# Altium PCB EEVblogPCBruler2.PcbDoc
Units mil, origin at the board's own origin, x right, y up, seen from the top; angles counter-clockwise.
Board outline 7000 x 836.61 mil, 2 copper layers (Top Layer, Bottom Layer); 0 components, 0 nets, 17 pads, 0 vias.
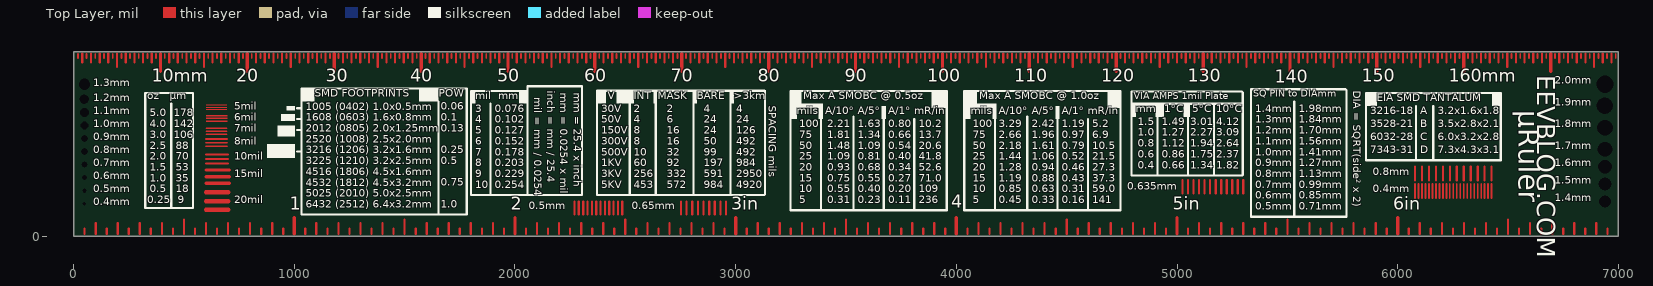
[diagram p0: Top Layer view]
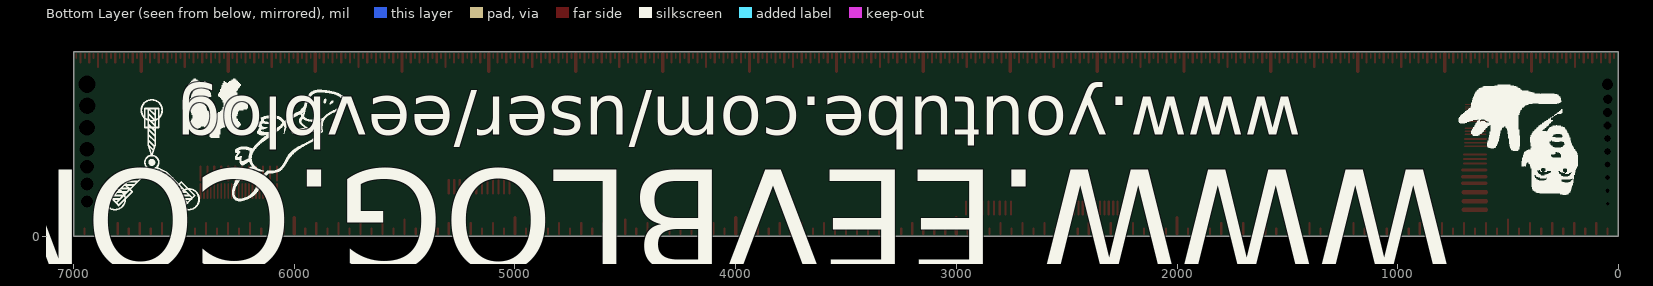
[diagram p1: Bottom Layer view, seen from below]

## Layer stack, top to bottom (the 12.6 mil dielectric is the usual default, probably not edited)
Top Layer: signal copper 1.4
Dielectric: dielectric 12.6, FR-4, Dk 4.8
Bottom Layer: signal copper 1.4

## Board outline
0,0 7000,0 7000,836.61 0,836.61

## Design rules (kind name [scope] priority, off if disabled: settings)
Clearance [All] p1: gap=10
PolygonConnect [All] p1: connectstyle=Relief reliefconductorwidth=10 reliefentries=4 polygonreliefangle="90 Angle"
RoutingVias [All] p1: holewidth=28 width=50 viastyle="Through Hole" minholewidth=28 minwidth=50 maxholewidth=28 maxwidth=50
SilkscreenOverComponentPads [All] p1: minsilkscreentomaskgap=10
SolderMaskExpansion [All] p1: expansion=4
Width [All] p1: maxlimit=10 minlimit=10 preferedwidth=10
27 further rules are at their usual default settings.

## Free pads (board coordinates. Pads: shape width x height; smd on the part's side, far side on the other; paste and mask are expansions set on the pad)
  rect 0x0 hole 15.75 unplated mask+2: 1(49.21,147.64)
  rect 0x0 hole 19.68 unplated mask+2: 2(49.21,206.69)
  rect 0x0 hole 23.62 unplated mask+2: 3(49.21,265.75)
  rect 0x0 hole 27.56 unplated mask+2: 4(49.21,324.8)
  rect 0x0 hole 31.5 unplated mask+2: 5(49.21,442.91) 6(49.21,383.86)
  rect 0x0 hole 35.43 unplated mask+2: 7(49.21,501.97)
  rect 0x0 hole 39.37 unplated mask+2: 8(49.21,561.02)
  rect 0x0 hole 43.31 unplated mask+2: 9(49.21,620.08)
  rect 0x0 hole 51.18 unplated mask+2: 10(49.21,688.98)
  rect 0x0 hole 55.12 unplated mask+2: 11(6938.98,157.48)
  rect 0x0 hole 59.06 unplated mask+2: 12(6938.98,236.22)
  rect 0x0 hole 62.99 unplated mask+2: 13(6938.98,314.96)
  rect 0x0 hole 66.93 unplated mask+2: 14(6938.98,393.7)
  rect 0x0 hole 70.87 unplated mask+2: 15(6938.98,492.13)
  rect 0x0 hole 74.8 unplated mask+2: 16(6938.98,590.55)
  rect 0x0 hole 78.74 unplated mask+2: 17(6938.98,688.98)

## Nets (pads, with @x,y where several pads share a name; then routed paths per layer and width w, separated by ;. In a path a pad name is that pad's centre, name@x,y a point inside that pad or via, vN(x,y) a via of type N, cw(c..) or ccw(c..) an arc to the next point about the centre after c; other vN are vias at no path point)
copper on no net: | length 23943.6
  Top Layer w5: 600,575 695,575 ; 600,585 695,585 ; 600,595 695,595
  Top Layer w6: 600,522 696,522 ; 600,534 696,534 ; 600,546 696,546
  Top Layer w7: 602,462 693,462 ; 602,476 693,476 ; 602,490 693,490
  Top Layer w8: 19.68,807.09 19.68,826.77 ; 59.06,807.09 59.06,826.77 ; 98.43,807.09 98.43,826.77 ; 137.8,807.09 137.8,826.77 ; 177.17,807.09 177.17,826.77 ; 216.54,807.09 216.54,826.77 ; 255.91,807.09 255.91,826.77 ; 295.28,807.09 295.28,826.77 ; 334.65,807.09 334.65,826.77 ; 374.02,807.09 374.02,826.77 ; 413.39,807.09 413.39,826.77 ; 452.76,807.09 452.76,826.77 ; 492.13,807.09 492.13,826.77 ; 531.5,807.09 531.5,826.77 ; 570.87,807.09 570.87,826.77 ; 600,408 696,408 ; 600,424 696,424 ; 600,440 696,440 ; 610.24,807.09 610.24,826.77 ; 649.61,807.09 649.61,826.77 ; 688.98,807.09 688.98,826.77 ; 728.35,807.09 728.35,826.77 ; 767.72,807.09 767.72,826.77 ; 807.09,807.09 807.09,826.77 ; 846.46,807.09 846.46,826.77 ; 885.83,807.09 885.83,826.77 ; 925.2,807.09 925.2,826.77 ; 964.57,807.09 964.57,826.77 ; 1003.94,807.09 1003.94,826.77 ; 1043.31,807.09 1043.31,826.77 ; 1082.68,807.09 1082.68,826.77 ; 1122.05,807.09 1122.05,826.77 ; 1161.42,807.09 1161.42,826.77 ; 1200.79,807.09 1200.79,826.77 ; 1240.16,807.09 1240.16,826.77 ; 1279.53,807.09 1279.53,826.77 ; 1318.9,807.09 1318.9,826.77 ; 1358.27,807.09 1358.27,826.77 ; 1397.64,807.09 1397.64,826.77 ; 1437.01,807.09 1437.01,826.77 ; 1476.38,807.09 1476.38,826.77 ; 1515.75,807.09 1515.75,826.77 ; 1555.12,807.09 1555.12,826.77 ; 1594.49,807.09 1594.49,826.77 ; 1633.86,807.09 1633.86,826.77 ; 1673.23,807.09 1673.23,826.77 ; 1712.6,807.09 1712.6,826.77 ; 1751.97,807.09 1751.97,826.77 ; 1791.34,807.09 1791.34,826.77 ; 1830.71,807.09 1830.71,826.77 ; 1870.08,807.09 1870.08,826.77 ; 1909.45,807.09 1909.45,826.77 ; 1948.82,807.09 1948.82,826.77 ; 1988.19,807.09 1988.19,826.77 ; 2027.56,807.09 2027.56,826.77 ; 2066.93,807.09 2066.93,826.77 ; 2106.3,807.09 2106.3,826.77 ; 2145.67,807.09 2145.67,826.77 ; 2185.04,807.09 2185.04,826.77 ; 2224.41,807.09 2224.41,826.77 ; 2263.78,807.09 2263.78,826.77 ; 2303.15,807.09 2303.15,826.77 ; 2342.52,807.09 2342.52,826.77 ; 2381.89,807.09 2381.89,826.77 ; 2421.26,807.09 2421.26,826.77 ; 2460.63,807.09 2460.63,826.77 ; 2500,807.09 2500,826.77 ; 2539.37,807.09 2539.37,826.77 ; 2578.74,807.09 2578.74,826.77 ; 2618.11,807.09 2618.11,826.77 ; 2657.48,807.09 2657.48,826.77 ; 2696.85,807.09 2696.85,826.77 ; 2736.22,807.09 2736.22,826.77 ; 2775.59,807.09 2775.59,826.77 ; 2814.96,807.09 2814.96,826.77 ; 2854.33,807.09 2854.33,826.77 ; 2893.7,807.09 2893.7,826.77 ; 2933.07,807.09 2933.07,826.77 ; 2972.44,807.09 2972.44,826.77 ; 3011.81,807.09 3011.81,826.77 ; 3051.18,807.09 3051.18,826.77 ; 3090.55,807.09 3090.55,826.77 ; 3129.92,807.09 3129.92,826.77 ; 3169.29,807.09 3169.29,826.77 ; 3208.66,807.09 3208.66,826.77 ; 3248.03,807.09 3248.03,826.77 ; 3287.4,807.09 3287.4,826.77 ; 3326.77,807.09 3326.77,826.77 ; 3366.14,807.09 3366.14,826.77 ; 3405.51,807.09 3405.51,826.77 ; 3444.88,807.09 3444.88,826.77 ; 3484.25,807.09 3484.25,826.77 ; 3523.62,807.09 3523.62,826.77 ; 3562.99,807.09 3562.99,826.77 ; 3602.36,807.09 3602.36,826.77 ; 3641.73,807.09 3641.73,826.77 ; 3681.1,807.09 3681.1,826.77 ; 3720.47,807.09 3720.47,826.77 ; 3759.84,807.09 3759.84,826.77 ; 3799.21,807.09 3799.21,826.77 ; 3838.58,807.09 3838.58,826.77 ; 3877.95,807.09 3877.95,826.77 ; 3917.32,807.09 3917.32,826.77 ; 3956.69,807.09 3956.69,826.77 ; 3996.06,807.09 3996.06,826.77 ; 4035.43,807.09 4035.43,826.77 ; 4074.8,807.09 4074.8,826.77 ; 4114.17,807.09 4114.17,826.77 ; 4153.54,807.09 4153.54,826.77 ; 4192.91,807.09 4192.91,826.77 ; 4232.28,807.09 4232.28,826.77 ; 4271.65,807.09 4271.65,826.77 ; 4311.02,807.09 4311.02,826.77 ; 4350.39,807.09 4350.39,826.77 ; 4389.76,807.09 4389.76,826.77 ; 4429.13,807.09 4429.13,826.77 ; 4468.5,807.09 4468.5,826.77 ; 4507.87,807.09 4507.87,826.77 ; 4547.24,807.09 4547.24,826.77 ; 4586.61,807.09 4586.61,826.77 ; 4625.98,807.09 4625.98,826.77 ; 4665.35,807.09 4665.35,826.77 ; 4704.72,807.09 4704.72,826.77 ; 4744.09,807.09 4744.09,826.77 ; 4783.46,807.09 4783.46,826.77 ; 4822.83,807.09 4822.83,826.77 ; 4862.2,807.09 4862.2,826.77 ; 4901.57,807.09 4901.57,826.77 ; 4940.94,807.09 4940.94,826.77 ; 4980.31,807.09 4980.31,826.77 ; 5019.69,807.09 5019.69,826.77 ; 5059.06,807.09 5059.06,826.77 ; 5098.43,807.09 5098.43,826.77 ; 5137.8,807.09 5137.8,826.77 ; 5177.17,807.09 5177.17,826.77 ; 5216.54,807.09 5216.54,826.77 ; 5255.91,807.09 5255.91,826.77 ; 5295.28,807.09 5295.28,826.77 ; 5334.65,807.09 5334.65,826.77 ; 5374.02,807.09 5374.02,826.77 ; 5413.39,807.09 5413.39,826.77 ; 5452.76,807.09 5452.76,826.77 ; 5492.13,807.09 5492.13,826.77 ; 5531.5,807.09 5531.5,826.77 ; 5570.87,807.09 5570.87,826.77 ; 5610.24,807.09 5610.24,826.77 ; 5649.61,807.09 5649.61,826.77 ; 5688.98,807.09 5688.98,826.77 ; 5728.35,807.09 5728.35,826.77 ; 5767.72,807.09 5767.72,826.77 ; 5807.09,807.09 5807.09,826.77 ; 5846.46,807.09 5846.46,826.77 ; 5885.83,807.09 5885.83,826.77 ; 5925.2,807.09 5925.2,826.77 ; 5964.57,807.09 5964.57,826.77 ; 6003.94,807.09 6003.94,826.77 ; 6043.31,807.09 6043.31,826.77 ; 6078.74,173.23 6078.74,236.22 ; 6082.68,807.09 6082.68,826.77 ; 6094.49,173.23 6094.49,236.22 ; 6110.24,173.23 6110.24,236.22 ; 6122.05,807.09 6122.05,826.77 ; 6125.98,173.23 6125.98,236.22 ; 6141.73,173.23 6141.73,236.22 ; 6157.48,173.23 6157.48,236.22 ; 6161.42,807.09 6161.42,826.77 ; 6173.23,173.23 6173.23,236.22 ; 6188.98,173.23 6188.98,236.22 ; 6200.79,807.09 6200.79,826.77 ; 6204.72,173.23 6204.72,236.22 ; 6220.47,173.23 6220.47,236.22 ; 6236.22,173.23 6236.22,236.22 ; 6240.16,807.09 6240.16,826.77 ; 6251.97,173.23 6251.97,236.22 ; 6267.72,173.23 6267.72,236.22 ; 6279.53,807.09 6279.53,826.77 ; 6283.46,173.23 6283.46,236.22 ; 6299.21,173.23 6299.21,236.22 ; 6314.96,173.23 6314.96,236.22 ; 6318.9,807.09 6318.9,826.77 ; 6330.71,173.23 6330.71,236.22 ; 6346.46,173.23 6346.46,236.22 ; 6358.27,807.09 6358.27,826.77 ; 6362.2,173.23 6362.2,236.22 ; 6377.95,173.23 6377.95,236.22 ; 6393.7,173.23 6393.7,236.22 ; 6397.64,807.09 6397.64,826.77 ; 6409.45,173.23 6409.45,236.22 ; 6425.2,173.23 6425.2,236.22 ; 6437.01,807.09 6437.01,826.77 ; 6476.38,807.09 6476.38,826.77 ; 6515.75,807.09 6515.75,826.77 ; 6555.12,807.09 6555.12,826.77 ; 6594.49,807.09 6594.49,826.77 ; 6633.86,807.09 6633.86,826.77 ; 6673.23,807.09 6673.23,826.77 ; 6712.6,807.09 6712.6,826.77 ; 6751.97,807.09 6751.97,826.77 ; 6791.34,807.09 6791.34,826.77 ; 6830.71,807.09 6830.71,826.77 ; 6870.08,807.09 6870.08,826.77 ; 6909.45,807.09 6909.45,826.77 ; 6948.82,807.09 6948.82,826.77 ; 6988.19,807.09 6988.19,826.77
  Top Layer w10: 39.37,787.4 39.37,826.77 ; 50,10 50,35 ; 78.74,787.4 78.74,826.77 ; 100,10 100,60 ; 118.11,787.4 118.11,826.77 ; 150,10 150,35 ; 157.48,787.4 157.48,826.77 ; 196.85,767.72 196.85,826.77 ; 200,10 200,60 ; 236.22,787.4 236.22,826.77 ; 250,10 250,35 ; 275.59,787.4 275.59,826.77 ; 300,10 300,60 ; 314.96,787.4 314.96,826.77 ; 350,10 350,35 ; 354.33,787.4 354.33,826.77 ; 400,10 400,60 ; 433.07,787.4 433.07,826.77 ; 450,10 450,35 ; 472.44,787.4 472.44,826.77 ; 500,10 500,75 ; 511.81,787.4 511.81,826.77 ; 550,10 550,35 ; 551.18,787.4 551.18,826.77 ; 590.55,767.72 590.55,826.77 ; 600,10 600,60 ; 600,330 700,330 ; 600,350 700,350 ; 600,370 700,370 ; 629.92,787.4 629.92,826.77 ; 650,10 650,35 ; 669.29,787.4 669.29,826.77 ; 700,10 700,60 ; 708.66,787.4 708.66,826.77 ; 748.03,787.4 748.03,826.77 ; 750,10 750,35 ; 800,10 800,60 ; 826.77,787.4 826.77,826.77 ; 850,10 850,35 ; 866.14,787.4 866.14,826.77 ; 900,10 900,60 ; 905.51,787.4 905.51,826.77 ; 944.88,787.4 944.88,826.77 ; 950,10 950,35 ; 984.25,767.72 984.25,826.77 ; 1023.62,787.4 1023.62,826.77 ; 1062.99,787.4 1062.99,826.77 ; 1102.36,787.4 1102.36,826.77 ; 1141.73,787.4 1141.73,826.77 ; 1220.47,787.4 1220.47,826.77 ; 1259.84,787.4 1259.84,826.77 ; 1299.21,787.4 1299.21,826.77 ; 1338.58,787.4 1338.58,826.77 ; 1377.95,767.72 1377.95,826.77 ; 1417.32,787.4 1417.32,826.77 ; 1456.69,787.4 1456.69,826.77 ; 1496.06,787.4 1496.06,826.77 ; 1535.43,787.4 1535.43,826.77 ; 1614.17,787.4 1614.17,826.77 ; 1653.54,787.4 1653.54,826.77 ; 1692.91,787.4 1692.91,826.77 ; 1732.28,787.4 1732.28,826.77 ; 1771.65,767.72 1771.65,826.77 ; 1811.02,787.4 1811.02,826.77 ; 1850.39,787.4 1850.39,826.77 ; 1889.76,787.4 1889.76,826.77 ; 1929.13,787.4 1929.13,826.77 ; 2007.87,787.4 2007.87,826.77 ; 2047.24,787.4 2047.24,826.77 ; 2050,10 2050,35 ; 2086.61,787.4 2086.61,826.77 ; 2100,10 2100,60 ; 2125.98,787.4 2125.98,826.77 ; 2150,10 2150,35 ; 2165.35,767.72 2165.35,826.77 ; 2200,10 2200,60 ; 2204.72,787.4 2204.72,826.77 ; 2244.09,787.4 2244.09,826.77 ; 2250,10 2250,35 ; 2269.69,98.43 2269.69,157.48 ; 2283.46,787.4 2283.46,826.77 ; 2289.37,98.43 2289.37,157.48 ; 2300,10 2300,60 ; 2309.06,98.43 2309.06,157.48 ; 2322.83,787.4 2322.83,826.77 ; 2328.74,98.43 2328.74,157.48 ; 2348.43,98.43 2348.43,157.48 ; 2350,10 2350,35 ; 2368.11,98.43 2368.11,157.48 ; 2387.8,98.43 2387.8,157.48 ; 2400,10 2400,60 ; 2401.57,787.4 2401.57,826.77 ; 2407.48,98.43 2407.48,157.48 ; 2427.17,98.43 2427.17,157.48 ; 2440.94,787.4 2440.94,826.77 ; 2446.85,98.43 2446.85,157.48 ; 2450,10 2450,35 ; 2466.54,98.43 2466.54,157.48 ; 2480.31,787.4 2480.31,826.77 ; 2486.22,98.43 2486.22,157.48 ; 2500,10 2500,75 ; 2519.69,787.4 2519.69,826.77 ; 2550,10 2550,35 ; 2559.06,767.72 2559.06,826.77 ; 2598.43,787.4 2598.43,826.77 ; 2600,10 2600,60 ; 2637.8,787.4 2637.8,826.77 ; 2650,10 2650,35 ; 2677.17,787.4 2677.17,826.77 ; 2700,10 2700,60 ; 2716.54,787.4 2716.54,826.77 ; 2750,10 2750,35 ; 2751.97,98.43 2751.97,157.48 ; 2777.56,98.43 2777.56,157.48 ; 2795.28,787.4 2795.28,826.77 ; 2800,10 2800,60 ; 2803.15,98.43 2803.15,157.48 ; 2828.74,98.43 2828.74,157.48 ; 2834.65,787.4 2834.65,826.77 ; 2850,10 2850,35 ; 2854.33,98.43 2854.33,157.48 ; 2874.02,787.4 2874.02,826.77 ; 2879.92,98.43 2879.92,157.48 ; 2900,10 2900,60 ; 2905.51,98.43 2905.51,157.48 ; 2913.39,787.4 2913.39,826.77 ; 2931.1,98.43 2931.1,157.48 ; 2950,10 2950,35 ; 2952.76,767.72 2952.76,826.77 ; 2956.69,98.43 2956.69,157.48 ; 2992.13,787.4 2992.13,826.77 ; 3031.5,787.4 3031.5,826.77 ; 3050,10 3050,35 ; 3070.87,787.4 3070.87,826.77 ; 3100,10 3100,60 ; 3110.24,787.4 3110.24,826.77 ; 3150,10 3150,35 ; 3188.98,787.4 3188.98,826.77 ; 3200,10 3200,60 ; 3228.35,787.4 3228.35,826.77 ; 3250,10 3250,35 ; 3267.72,787.4 3267.72,826.77 ; 3300,10 3300,60 ; 3307.09,787.4 3307.09,826.77 ; 3346.46,767.72 3346.46,826.77 ; 3350,10 3350,35 ; 3385.83,787.4 3385.83,826.77 ; 3400,10 3400,60 ; 3425.2,787.4 3425.2,826.77 ; 3450,10 3450,35 ; 3464.57,787.4 3464.57,826.77 ; 3500,10 3500,75 ; 3503.94,787.4 3503.94,826.77 ; 3550,10 3550,35 ; 3582.68,787.4 3582.68,826.77 ; 3600,10 3600,60 ; 3622.05,787.4 3622.05,826.77 ; 3650,10 3650,35 ; 3661.42,787.4 3661.42,826.77 ; 3700,10 3700,60 ; 3700.79,787.4 3700.79,826.77 ; 3740.16,767.72 3740.16,826.77 ; 3750,10 3750,35 ; 3779.53,787.4 3779.53,826.77 ; 3800,10 3800,60 ; 3818.9,787.4 3818.9,826.77 ; 3850,10 3850,35 ; 3858.27,787.4 3858.27,826.77 ; 3897.64,787.4 3897.64,826.77 ; 3900,10 3900,60 ; 3950,10 3950,35 ; 3976.38,787.4 3976.38,826.77 ; 4015.75,787.4 4015.75,826.77 ; 4050,10 4050,35 ; 4055.12,787.4 4055.12,826.77 ; 4094.49,787.4 4094.49,826.77 ; 4100,10 4100,60 ; 4133.86,767.72 4133.86,826.77 ; 4150,10 4150,35 ; 4173.23,787.4 4173.23,826.77 ; 4200,10 4200,60 ; 4212.6,787.4 4212.6,826.77 ; 4250,10 4250,35 ; 4251.97,787.4 4251.97,826.77 ; 4291.34,787.4 4291.34,826.77 ; 4300,10 4300,60 ; 4350,10 4350,35 ; 4370.08,787.4 4370.08,826.77 ; 4400,10 4400,60 ; 4409.45,787.4 4409.45,826.77 ; 4448.82,787.4 4448.82,826.77 ; 4450,10 4450,35 ; 4488.19,787.4 4488.19,826.77 ; 4500,10 4500,75 ; 4527.56,767.72 4527.56,826.77 ; 4550,10 4550,35 ; 4566.93,787.4 4566.93,826.77 ; 4600,10 4600,60 ; 4606.3,787.4 4606.3,826.77 ; 4645.67,787.4 4645.67,826.77 ; 4650,10 4650,35 ; 4685.04,787.4 4685.04,826.77 ; 4700,10 4700,60 ; 4750,10 4750,35 ; 4763.78,787.4 4763.78,826.77 ; 4800,10 4800,60 ; 4803.15,787.4 4803.15,826.77 ; 4842.52,787.4 4842.52,826.77 ; 4850,10 4850,35 ; 4881.89,787.4 4881.89,826.77 ; 4900,10 4900,60 ; 4921.26,767.72 4921.26,826.77 ; 4950,10 4950,35 ; 4960.63,787.4 4960.63,826.77 ; 5000,787.4 5000,826.77 ; 5025,194.68 5025,253.74 ; 5039.37,787.4 5039.37,826.77 ; 5050,10 5050,35 ; 5050,194.68 5050,253.74 ; 5075,194.68 5075,253.74 ; 5078.74,787.4 5078.74,826.77 ; 5100,10 5100,60 ; 5100,194.68 5100,253.74 ; 5125,194.68 5125,253.74 ; 5150,10 5150,35 ; 5150,194.68 5150,253.74 ; 5157.48,787.4 5157.48,826.77 ; 5175,194.68 5175,253.74 ; 5196.85,787.4 5196.85,826.77 ; 5200,10 5200,60 ; 5200,194.68 5200,253.74 ; 5225,194.68 5225,253.74 ; 5236.22,787.4 5236.22,826.77 ; 5250,10 5250,35 ; 5250,194.68 5250,253.74 ; 5275,194.68 5275,253.74 ; 5275.59,787.4 5275.59,826.77 ; 5300,10 5300,60 ; 5300,194.68 5300,253.74 ; 5314.96,767.72 5314.96,826.77 ; 5350,10 5350,35 ; 5354.33,787.4 5354.33,826.77 ; 5393.7,787.4 5393.7,826.77 ; 5400,10 5400,60 ; 5433.07,787.4 5433.07,826.77 ; 5450,10 5450,35 ; 5472.44,787.4 5472.44,826.77 ; 5500,10 5500,75 ; 5550,10 5550,35 ; 5551.18,787.4 5551.18,826.77 ; 5590.55,787.4 5590.55,826.77 ; 5600,10 5600,60 ; 5629.92,787.4 5629.92,826.77 ; 5650,10 5650,35 ; 5669.29,787.4 5669.29,826.77 ; 5700,10 5700,60 ; 5708.66,767.72 5708.66,826.77 ; 5748.03,787.4 5748.03,826.77 ; 5750,10 5750,35 ; 5787.4,787.4 5787.4,826.77 ; 5800,10 5800,60 ; 5826.77,787.4 5826.77,826.77 ; 5850,10 5850,35 ; 5866.14,787.4 5866.14,826.77 ; 5900,10 5900,60 ; 5944.88,787.4 5944.88,826.77 ; 5950,10 5950,35 ; 5984.25,787.4 5984.25,826.77 ; 6023.62,787.4 6023.62,826.77 ; 6050,10 6050,35 ; 6062.99,787.4 6062.99,826.77 ; 6078.74,251.97 6078.74,314.96 ; 6100,10 6100,60 ; 6102.36,767.72 6102.36,826.77 ; 6110.24,251.97 6110.24,314.96 ; 6141.73,251.97 6141.73,314.96 ; 6141.73,787.4 6141.73,826.77 ; 6150,10 6150,35 ; 6173.23,251.97 6173.23,314.96 ; 6181.1,787.4 6181.1,826.77 ; 6200,10 6200,60 ; 6204.72,251.97 6204.72,314.96 ; 6220.47,787.4 6220.47,826.77 ; 6236.22,251.97 6236.22,314.96 ; 6250,10 6250,35 ; 6259.84,787.4 6259.84,826.77 ; 6267.72,251.97 6267.72,314.96 ; 6299.21,251.97 6299.21,314.96 ; 6300,10 6300,60 ; 6330.71,251.97 6330.71,314.96 ; 6338.58,787.4 6338.58,826.77 ; 6350,10 6350,35 ; 6362.2,251.97 6362.2,314.96 ; 6377.95,787.4 6377.95,826.77 ; 6393.7,251.97 6393.7,314.96 ; 6400,10 6400,60 ; 6417.32,787.4 6417.32,826.77 ; 6425.2,251.97 6425.2,314.96 ; 6450,10 6450,35 ; 6456.69,787.4 6456.69,826.77 ; 6496.06,767.72 6496.06,826.77 ; 6500,10 6500,75 ; 6535.43,787.4 6535.43,826.77 ; 6550,10 6550,35 ; 6574.8,787.4 6574.8,826.77 ; 6600,10 6600,60 ; 6614.17,787.4 6614.17,826.77 ; 6650,10 6650,35 ; 6653.54,787.4 6653.54,826.77 ; 6700,10 6700,60 ; 6732.28,787.4 6732.28,826.77 ; 6750,10 6750,35 ; 6771.65,787.4 6771.65,826.77 ; 6800,10 6800,60 ; 6811.02,787.4 6811.02,826.77 ; 6850,10 6850,35 ; 6850.39,787.4 6850.39,826.77 ; 6889.76,767.72 6889.76,826.77 ; 6900,10 6900,60 ; 6929.13,787.4 6929.13,826.77 ; 6950,10 6950,35 ; 6968.5,787.4 6968.5,826.77 ; 1050,10 1050,35 1050,10 ; 1100,10 1100,60 1100,10 ; 1150,10 1150,35 1150,10 ; 1200,10 1200,60 1200,10 ; 1250,10 1250,35 1250,10 ; 1300,10 1300,60 1300,10 ; 1350,10 1350,35 1350,10 ; 1400,10 1400,60 1400,10 ; 1450,10 1450,35 1450,10 ; 1500,10 1500,75 1500,10 ; 1550,10 1550,35 1550,10 ; 1600,10 1600,60 1600,10 ; 1650,10 1650,35 1650,10 ; 1700,10 1700,60 1700,10 ; 1750,10 1750,35 1750,10 ; 1800,10 1800,60 1800,10 ; 1850,10 1850,35 1850,10 ; 1900,10 1900,60 1900,10 ; 1950,10 1950,35 1950,10
  Top Layer w15: 393.7,748.03 393.7,826.77 ; 600,239.84 705,239.84 ; 600,269.84 705,269.84 ; 600,299.84 705,299.84 ; 787.4,748.03 787.4,826.77 ; 1000,10 1000,85 ; 1181.1,748.03 1181.1,826.77 ; 1574.8,748.03 1574.8,826.77 ; 1968.5,748.03 1968.5,826.77 ; 2362.2,748.03 2362.2,826.77 ; 2755.91,748.03 2755.91,826.77 ; 3000,10 3000,85 ; 3149.61,748.03 3149.61,826.77 ; 3543.31,748.03 3543.31,826.77 ; 3937.01,748.03 3937.01,826.77 ; 4000,10 4000,85 ; 4330.71,748.03 4330.71,826.77 ; 4724.41,748.03 4724.41,826.77 ; 5000,10 5000,85 ; 5118.11,748.03 5118.11,826.77 ; 5511.81,748.03 5511.81,826.77 ; 5905.51,748.03 5905.51,826.77 ; 6000,10 6000,85 ; 6299.21,748.03 6299.21,826.77 ; 6692.91,748.03 6692.91,826.77 ; 2000,10 2000,85 2000,10
  Top Layer w20: 600,120 700,120 ; 600,159.37 700,159.37 ; 600,199.37 700,199.37

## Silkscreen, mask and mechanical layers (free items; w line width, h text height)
Top Overlay:
  rectangle: 2972.44,600.39 2992.13,659.45
  rectangle: 2805.12,600.39 2824.8,659.45
  rectangle: 2627.95,600.39 2637.8,659.45
  rectangle: 2460.63,600.39 2539.37,659.45
  rectangle: 2372.05,600.39 2411.42,659.45
  rectangle: 4685.04,580.71 4744.09,658.61
  rectangle: 4035.43,589.28 4094.49,658.61
  rectangle: 3887.8,580.71 3956.69,658.61
  rectangle: 3252.19,589.28 3297.24,654.46
  rectangle: 4035.43,531.5 4064.96,590.55
  rectangle: 4163.39,530.81 4183.07,600.39
  rectangle: 4448.82,531.5 4468.5,590.55
  rectangle: 4045.28,580.71 4173.23,600.39
  rectangle: 3257.87,580.71 3385.83,600.39
  rectangle: 3661.42,531.5 3681.1,590.55
  rectangle: 3375.98,530.8 3395.67,600.39
  rectangle: 3248.03,531.5 3277.56,590.55
  rectangle: 6427.17,590.55 6466.54,649.61
  rectangle: 5856.3,590.55 5905.51,649.61
  rectangle: 2017.72,600.39 2057.09,657.92
  rectangle: 1801.18,600.39 1820.87,657.92
  rectangle: 4803.15,589.02 4910.1,600.39
  rectangle: 4793.31,541.34 4812.99,599.75
  rectangle: 4901.57,541.34 4940.94,600.39
  rectangle: 5029.53,540.65 5059.06,600.39
  rectangle: 1564.09,609.76 1653.54,668.82
  rectangle: 1032.6,609.76 1091.65,668.82
  rectangle: 877.09,353.86 1003.07,416.85
  rectangle: 924.33,452.28 1003.07,501.5
  rectangle: 940.08,521.18 1003.07,552.68
  rectangle: 963.7,570.39 1003.07,590.08
  lines w10: 442.91,127.95 442.91,600.39 ; 1012.91,383.39 1032.6,383.39 ; 1012.91,481.81 1032.6,481.81 ; 1012.91,531.02 1032.6,531.02 ; 1012.91,580.24 1032.6,580.24 ; 1653.54,97.95 1653.54,609.76 ; 1889.76,187.01 1889.76,600.39 ; 2057.09,206.69 2057.09,677.61 ; 2057.09,657.92 1801.18,657.92 1801.18,187.01 2057.09,187.01 ; 2519.69,187.01 2519.69,659.45 ; 2637.8,187.01 2637.8,658.56 ; 2809.14,187.01 2809.14,658.56 ; 2976.25,187.01 2976.25,659.45 ; 3252.19,654.46 3248.03,658.61 ; 3387.28,119.56 3387.28,530.8 ; 3533.46,118.11 3533.46,541.34 ; 3671.26,118.11 3671.26,530.86 ; 3809.06,118.11 3809.06,531.5 ; 4039.59,654.46 4035.43,658.61 ; 4174.68,119.56 4174.68,530.81 ; 4320.87,118.11 4320.87,541.34 ; 4458.66,118.11 4458.66,530.86 ; 4596.46,118.11 4596.46,531.5 ; 4793.31,580.71 4793.31,656.02 5293.64,656.02 ; 4911.42,275.59 4911.42,600.39 ; 5049.21,275.59 5049.21,600.39 ; 5167.32,275.59 5167.32,599.5 ; 5298.12,580.71 5298.12,651.54 ; 5531.5,88.58 5531.5,610.24 ; 6082.68,344.49 6082.68,590.55 ; 6161.42,344.49 6161.42,590.55 ; 2057.09,187.01 2303.15,187.01 2303.15,679.13 2057.09,679.13 2057.09,187.01 ; 2976.25,659.45 3131.25,659.45 3132.66,658.04 3132.66,189.75 3129.92,187.01 2962.6,187.01 2372.05,187.01 2372.05,659.45 2976.25,659.45 ; 3248.03,658.61 3956.69,658.61 3956.69,118.11 3248.03,118.11 3248.03,658.61 ; 4035.43,658.61 4035.43,118.11 4744.09,118.11 4744.09,658.61 4035.43,658.61 ; 324.8,127.95 324.8,649.61 541.34,649.61 541.34,127.95 324.8,127.95 ; 1032.6,97.95 1781.5,97.95 1781.5,668.82 1032.6,668.82 1032.6,97.95 ; 4793.31,275.59 5295.28,275.59 5298.12,278.43 5298.12,599.5 5299.01,600.39 4793.31,600.39 4793.31,275.59 ; 5334.65,88.58 5767.72,88.58 5767.72,661.46 5763.32,665.86 5334.65,665.86 5334.65,88.58 ; 5856.3,344.49 6466.54,344.49 6466.54,649.61 5856.3,649.61 5856.3,344.49
  text "EEVBLOG.COM" at 6604.33,728.35 h137.8 r270
  text "10mm" at 354.33,679.13 h98.43
  text "20" at 738.19,679.13 h98.43
  text "30" at 1141.73,679.13 h98.43
  text "40" at 1525.59,679.13 h98.43
  text "50" at 1919.29,679.13 h98.43
  text "60" at 2312.99,679.13 h98.43
  text "70" at 2706.69,679.13 h98.43
  text "80" at 3100.39,679.13 h98.43
  text "90" at 3494.09,679.13 h98.43
  text "100" at 3868.11,679.13 h98.43
  text "110" at 4261.81,679.13 h98.43
  text "120" at 4655.51,679.13 h98.43
  text "130" at 5049.21,679.13 h98.43
  text "150" at 5836.61,679.13 h98.43
  text "160mm" at 6230.32,679.13 h98.43
  text "2.0mm" at 6712.6,679.13 h59.06
  text "140" at 5442.91,675.7 h98.43
  text "1.3mm" at 88.58,669.29 h59.06
  text "inch = mm / 25.4" at 2135.83,659.45 h59.06 r270
  text "DIA = SQRT(side² x 2)" at 5787.4,659.45 h59.06 r270
  text "mm = 0.0254 x mil" at 2194.88,649.61 h59.06 r270
  text "mm = 25.4 x inch" at 2253.94,649.61 h59.06 r270
  text "mil = mm / 0.0254" at 2076.77,629.92 h59.06 r270
  text "SMD FOOTPRINTS" at 1091.65,619.61 h59.06
  text "POW" at 1653.54,620.08 h59.06
  text "SQ PIN to DIAmm" at 5344.49,620.08 h55.12
  text "oz   µm" at 334.65,610.24 h59.06
  text "mil  mm" at 1820.87,610.24 h59.06
  text "V" at 2421.26,610.24 h59.06
  text "INT" at 2539.37,610.24 h59.06
  text "MASK" at 2647.64,610.24 h59.06
  text "BARE" at 2824.8,610.24 h59.06
  text ">3km" at 2992.13,610.24 h59.06
  text "Max A SMOBC @ 0.5oz" at 3307.09,610.24 h59.06
  text "Max A SMOBC @ 1.0oz" at 4104.33,610.24 h59.06
  text "VIA AMPS 1mil Plate" at 4803.15,610.24 h55.12
  text "1.2mm" at 88.58,600.39 h59.06
  text "EIA SMD TANTALUM" at 5905.51,600.39 h59.06
  text "SPACING mils" at 3139.76,590.55 h59.06 r270
  text "1.9mm" at 6712.6,580.71 h59.06
  text "µRuler" at 6515.75,570.87 h157.48 r270
  text "5mil" at 728.35,561.02 h59.06
  text "1005 (0402) 1.0x0.5mm" at 1052.28,560.55 h59.06
  text "0.06" at 1663.39,561.02 h59.06
  text "3" at 1820.87,551.18 h59.06
  text "0.076" at 1909.45,551.18 h59.06
  text "30V" at 2391.73,551.18 h59.06
  text "2" at 2539.37,551.18 h59.06
  text "2" at 2687.01,551.18 h59.06
  text "4" at 2854.33,551.18 h59.06
  text "4" at 3001.97,551.18 h59.06
  text "mm" at 4812.99,551.18 h59.06
  text "1°C" at 4940.94,551.18 h59.06
  text "5°C" at 5068.9,551.18 h59.06
  text "10°C" at 5177.17,551.18 h59.06
  text "1.4mm" at 5354.33,551.18 h59.06
  text "1.98mm" at 5551.18,551.18 h59.06
  text "1.1mm" at 88.58,541.34 h59.06
  text "mils" at 3277.56,541.34 h59.06
  text "A/10°" at 3405.51,541.34 h59.06
  text "A/5°" at 3553.15,541.34 h59.06
  text "A/1°" at 3690.94,541.34 h59.06
  text "mR/in" at 3809.06,541.34 h59.06
  text "mils" at 4064.96,541.34 h59.06
  text "A/10°" at 4192.91,541.34 h59.06
  text "A/5°" at 4340.55,541.34 h59.06
  text "A/1°" at 4478.35,541.34 h59.06
  text "mR/in" at 4596.46,541.34 h59.06
  text "3216-18" at 5875.98,541.34 h59.06
  text "A" at 6102.36,541.34 h59.06
  text "3.2x1.6x1.8" at 6181.1,541.34 h59.06
  text "5.0" at 344.49,531.5 h59.06
  text "178" at 452.76,531.5 h59.06
  text "6mil" at 728.35,511.81 h59.06
  text "0.1" at 1663.39,511.81 h59.06
  text "1608 (0603) 1.6x0.8mm" at 1052.28,511.34 h59.06
  text "4" at 1820.87,501.97 h59.06
  text "0.102" at 1909.45,501.97 h59.06
  text "50V" at 2391.73,501.97 h59.06
  text "4" at 2539.37,501.97 h59.06
  text "6" at 2687.01,501.97 h59.06
  text "24" at 2854.33,501.97 h59.06
  text "24" at 3001.97,501.97 h59.06
  text "1.3mm" at 5354.33,501.97 h59.06
  text "1.84mm" at 5551.18,501.97 h59.06
  text "1.5" at 4822.83,492.13 h59.06
  text "1.49" at 4931.1,492.13 h59.06
  text "3.01" at 5059.06,492.13 h59.06
  text "4.12" at 5177.17,492.13 h59.06
  text "1.0mm" at 88.58,482.28 h59.06
  text "4.0" at 344.49,482.28 h59.06
  text "142" at 452.76,482.28 h59.06
  text "100" at 3287.4,482.28 h59.06
  text "2.21" at 3415.35,482.28 h59.06
  text "1.63" at 3553.15,482.28 h59.06
  text "0.80" at 3690.94,482.28 h59.06
  text "10.2" at 3828.74,482.28 h59.06
  text "100" at 4074.8,482.28 h59.06
  text "3.29" at 4192.91,482.28 h59.06
  text "2.42" at 4340.55,482.28 h59.06
  text "1.19" at 4478.35,482.28 h59.06
  text "5.2" at 4616.14,482.28 h59.06
  text "3528-21" at 5875.98,482.28 h59.06
  text "B" at 6102.36,482.28 h59.06
  text "3.5x2.8x2.1" at 6181.1,482.28 h59.06
  text "1.8mm" at 6712.6,482.28 h59.06
  text "7mil" at 728.35,462.6 h59.06
  text "0.13" at 1663.39,462.6 h59.06
  text "2012 (0805) 2.0x1.25mm" at 1052.28,462.13 h59.06
  text "5" at 1820.87,452.76 h59.06
  text "0.127" at 1909.45,452.76 h59.06
  text "150V" at 2391.73,452.76 h59.06
  text "8" at 2539.37,452.76 h59.06
  text "16" at 2687.01,452.76 h59.06
  text "24" at 2854.33,452.76 h59.06
  text "126" at 3001.97,452.76 h59.06
  text "1.2mm" at 5354.33,452.76 h59.06
  text "1.70mm" at 5551.18,452.76 h59.06
  text "1.0" at 4822.83,442.91 h59.06
  text "1.27" at 4931.1,442.91 h59.06
  text "2.27" at 5059.06,442.91 h59.06
  text "3.09" at 5177.17,442.91 h59.06
  text "3.0" at 344.49,433.07 h59.06
  text "106" at 452.76,433.07 h59.06
  text "75" at 3287.4,433.07 h59.06
  text "1.81" at 3415.35,433.07 h59.06
  text "1.34" at 3553.15,433.07 h59.06
  text "0.66" at 3690.94,433.07 h59.06
  text "13.7" at 3828.74,433.07 h59.06
  text "75" at 4074.8,433.07 h59.06
  text "2.66" at 4192.91,433.07 h59.06
  text "1.96" at 4340.55,433.07 h59.06
  text "0.97" at 4478.35,433.07 h59.06
  text "6.9" at 4616.14,433.07 h59.06
  text "0.9mm" at 88.58,423.23 h59.06
  text "6032-28" at 5875.98,423.23 h59.06
  text "C" at 6102.36,423.23 h59.06
  text "6.0x3.2x2.8" at 6181.1,423.23 h59.06
  text "2520 (1008) 2.5x2.0mm" at 1052.28,412.91 h59.06
  text "8mil" at 728.35,403.54 h59.06
  text "6" at 1820.87,403.54 h59.06
  text "0.152" at 1909.45,403.54 h59.06
  text "300V" at 2391.73,403.54 h59.06
  text "8" at 2539.37,403.54 h59.06
  text "16" at 2687.01,403.54 h59.06
  text "50" at 2854.33,403.54 h59.06
  text "492" at 3001.97,403.54 h59.06
  text "1.1mm" at 5354.33,403.54 h59.06
  text "1.56mm" at 5551.18,403.54 h59.06
  text "0.8" at 4822.83,393.7 h59.06
  text "1.12" at 4931.1,393.7 h59.06
  text "1.94" at 5059.06,393.7 h59.06
  text "2.64" at 5177.17,393.7 h59.06
  text "2.5" at 344.49,383.86 h59.06
  text "88" at 462.6,383.86 h59.06
  text "50" at 3287.4,383.86 h59.06
  text "1.48" at 3415.35,383.86 h59.06
  text "1.09" at 3553.15,383.86 h59.06
  text "0.54" at 3690.94,383.86 h59.06
  text "20.6" at 3828.74,383.86 h59.06
  text "50" at 4074.8,383.86 h59.06
  text "2.18" at 4192.91,383.86 h59.06
  text "1.61" at 4340.55,383.86 h59.06
  text "0.79" at 4478.35,383.86 h59.06
  text "10.5" at 4616.14,383.86 h59.06
  text "1.7mm" at 6712.6,383.86 h59.06
  text "0.8mm" at 88.58,364.17 h59.06
  text "3216 (1206) 3.2x1.6mm" at 1052.28,363.7 h59.06
  text "0.25" at 1663.39,364.17 h59.06
  text "7343-31" at 5875.98,364.17 h59.06
  text "D" at 6102.36,364.17 h59.06
  text "7.3x4.3x3.1" at 6181.1,364.17 h59.06
  text "7" at 1820.87,354.33 h59.06
  text "0.178" at 1909.45,354.33 h59.06
  text "500V" at 2391.73,354.33 h59.06
  text "10" at 2539.37,354.33 h59.06
  text "32" at 2687.01,354.33 h59.06
  text "99" at 2854.33,354.33 h59.06
  text "492" at 3001.97,354.33 h59.06
  text "1.0mm" at 5354.33,354.33 h59.06
  text "1.41mm" at 5551.18,354.33 h59.06
  text "0.6" at 4822.83,344.49 h59.06
  text "0.86" at 4931.1,344.49 h59.06
  text "1.75" at 5059.06,344.49 h59.06
  text "2.37" at 5177.17,344.49 h59.06
  text "2.0" at 344.49,334.65 h59.06
  text "70" at 462.6,334.65 h59.06
  text "10mil" at 728.35,334.65 h59.06
  text "25" at 3287.4,334.65 h59.06
  text "1.09" at 3415.35,334.65 h59.06
  text "0.81" at 3553.15,334.65 h59.06
  text "0.40" at 3690.94,334.65 h59.06
  text "41.8" at 3828.74,334.65 h59.06
  text "25" at 4074.8,334.65 h59.06
  text "1.44" at 4192.91,334.65 h59.06
  text "1.06" at 4340.55,334.65 h59.06
  text "0.52" at 4478.35,334.65 h59.06
  text "21.5" at 4616.14,334.65 h59.06
  text "0.5" at 1663.39,314.96 h59.06
  text "3225 (1210) 3.2x2.5mm" at 1052.28,314.49 h59.06
  text "0.7mm" at 88.58,305.12 h59.06
  text "8" at 1820.87,305.12 h59.06
  text "0.203" at 1909.45,305.12 h59.06
  text "1KV" at 2391.73,305.12 h59.06
  text "60" at 2539.37,305.12 h59.06
  text "92" at 2687.01,305.12 h59.06
  text "197" at 2854.33,305.12 h59.06
  text "984" at 3001.97,305.12 h59.06
  text "0.9mm" at 5354.33,305.12 h59.06
  text "1.27mm" at 5551.18,305.12 h59.06
  text "1.6mm" at 6712.6,305.12 h59.06
  text "0.4" at 4822.83,295.28 h59.06
  text "0.66" at 4931.1,295.28 h59.06
  text "1.34" at 5059.06,295.28 h59.06
  text "1.82" at 5177.17,295.28 h59.06
  text "1.5" at 344.49,285.43 h59.06
  text "53" at 462.6,285.43 h59.06
  text "20" at 3287.4,285.43 h59.06
  text "0.93" at 3415.35,285.43 h59.06
  text "0.68" at 3553.15,285.43 h59.06
  text "0.34" at 3690.94,285.43 h59.06
  text "52.6" at 3828.74,285.43 h59.06
  text "20" at 4074.8,285.43 h59.06
  text "1.28" at 4192.91,285.43 h59.06
  text "0.94" at 4340.55,285.43 h59.06
  text "0.46" at 4478.35,285.43 h59.06
  text "27.3" at 4616.14,285.43 h59.06
  text "0.8mm" at 5885.83,265.75 h59.06
  text "4516 (1806) 4.5x1.6mm" at 1052.28,265.28 h59.06
  text "15mil" at 728.35,255.91 h59.06
  text "9" at 1820.87,255.91 h59.06
  text "0.229" at 1909.45,255.91 h59.06
  text "3KV" at 2391.73,255.91 h59.06
  text "256" at 2539.37,255.91 h59.06
  text "332" at 2687.01,255.91 h59.06
  text "591" at 2854.33,255.91 h59.06
  text "2950" at 3001.97,255.91 h59.06
  text "0.8mm" at 5354.33,255.91 h59.06
  text "1.13mm" at 5551.18,255.91 h59.06
  text "0.6mm" at 88.58,246.06 h59.06
  text "1.0" at 344.49,236.22 h59.06
  text "35" at 462.6,236.22 h59.06
  text "15" at 3287.4,236.22 h59.06
  text "0.75" at 3415.35,236.22 h59.06
  text "0.55" at 3553.15,236.22 h59.06
  text "0.27" at 3690.94,236.22 h59.06
  text "71.0" at 3828.74,236.22 h59.06
  text "15" at 4074.8,236.22 h59.06
  text "1.19" at 4192.91,236.22 h59.06
  text "0.88" at 4340.55,236.22 h59.06
  text "0.43" at 4478.35,236.22 h59.06
  text "37.3" at 4616.14,236.22 h59.06
  text "1.5mm" at 6712.6,226.38 h59.06
  text "0.75" at 1663.39,216.54 h59.06
  text "4532 (1812) 4.5x3.2mm" at 1052.28,216.06 h59.06
  text "10" at 1820.87,206.69 h59.06
  text "0.254" at 1909.45,206.69 h59.06
  text "5KV" at 2391.73,206.69 h59.06
  text "453" at 2539.37,206.69 h59.06
  text "572" at 2687.01,206.69 h59.06
  text "984" at 2854.33,206.69 h59.06
  text "4920" at 3001.97,206.69 h59.06
  text "0.7mm" at 5354.33,206.69 h59.06
  text "0.99mm" at 5551.18,206.69 h59.06
  text "0.635mm" at 4775,200 h59.06
  text "0.5mm" at 88.58,187.01 h59.06
  text "0.5" at 344.49,187.01 h59.06
  text "18" at 462.6,187.01 h59.06
  text "10" at 3287.4,187.01 h59.06
  text "0.55" at 3415.35,187.01 h59.06
  text "0.40" at 3553.15,187.01 h59.06
  text "0.20" at 3690.94,187.01 h59.06
  text "109" at 3828.74,187.01 h59.06
  text "10" at 4074.8,187.01 h59.06
  text "0.85" at 4192.91,187.01 h59.06
  text "0.63" at 4340.55,187.01 h59.06
  text "0.31" at 4478.35,187.01 h59.06
  text "59.0" at 4616.14,187.01 h59.06
  text "0.4mm" at 5885.83,187.01 h59.06
  text "5025 (2010) 5.0x2.5mm" at 1052.28,166.85 h59.06
  text "0.6mm" at 5354.33,157.48 h59.06
  text "0.85mm" at 5551.18,157.48 h59.06
  text "1.4mm" at 6712.6,147.64 h59.06
  text "0.25" at 334.65,137.8 h59.06
  text "9" at 472.44,137.8 h59.06
  text "20mil" at 728.35,137.8 h59.06
  text "5" at 3287.4,137.8 h59.06
  text "0.31" at 3415.35,137.8 h59.06
  text "0.23" at 3553.15,137.8 h59.06
  text "0.11" at 3690.94,137.8 h59.06
  text "236" at 3828.74,137.8 h59.06
  text "5" at 4074.8,137.8 h59.06
  text "0.45" at 4192.91,137.8 h59.06
  text "0.33" at 4340.55,137.8 h59.06
  text "0.16" at 4478.35,137.8 h59.06
  text "141" at 4616.14,137.8 h59.06
  text "0.4mm" at 88.58,127.95 h59.06
  text "6432 (2512) 6.4x3.2mm" at 1052.28,117.64 h59.06
  text "1.0" at 1663.39,118.11 h59.06
  text "0.5mm" at 2062.2,110.24 h59.06
  text "0.65mm" at 2528.74,110.24 h59.06
  text "4" at 3976.38,108.27 h98.43
  text "0.5mm" at 5354.33,108.27 h59.06
  text "0.71mm" at 5551.18,108.27 h59.06
  text "1" at 980,100 h98.43
  text "2" at 1980,100 h98.43
  text "3in" at 2980,100 h98.43
  text "5in" at 4980,100 h98.43
  text "6in" at 5980,100 h98.43
Bottom Overlay:
  drawing of 2038 lines, arcs and shapes, not listed
  text "www.youtube.com/user/eevblog" at 1437.01,708.66 h393.7 r180
  text "WWW.EEVBLOG.COM" at 748.03,452.76 h787.4 r180
Top Solder:
  rectangle: 6062.99,177.17 6437.01,236.22
  rectangle: 6062.99,255.91 6437.01,314.96
  rectangle: 5009.84,196.85 5314.96,246.06
  rectangle: 2250,98.43 2496.06,157.48
  rectangle: 2736.22,98.43 2972.44,157.48
  rectangle: 580,100 720,614.17
  rectangle: 0,0 7000,80
  rectangle: 0,752.36 7000,852.36
  rectangle: 0,19.68 78.74,767.72
  rectangle: 6881.89,29.53 7000,797.24
Mechanical 1:
  the board outline again, w10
